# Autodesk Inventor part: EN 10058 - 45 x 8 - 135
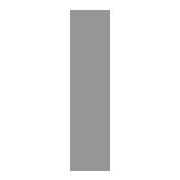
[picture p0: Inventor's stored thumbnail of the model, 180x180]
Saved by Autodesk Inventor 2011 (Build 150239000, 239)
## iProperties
IsCustomPart: 1
Created: 2010-02
Part Number: EN 10058 - 45 x 8 - 135
Material: Steel, A36
Description: flat steel bar 45*8
Document SubType Name: Modeling
Standard: DIN
Designer: PC
Standard Revision: 2004
Standards Organization: DIN
Language: en-US
Size Designation: 45 x 8
Categories: <MemberInstance><Categories><Category DisplayName="Structural Shapes" InternalName="089c4875-fa83-4c05-b084-43b9cc11f5ed" Mnemonic="GRDR"><CategoryParameter Dis
Stock Number: 45 x 8
Density: 7.85 g/cm^3
_CCFamilyMember: 49
_CCFamilyDisplayName: DIN EN 10058 - Hot rolled flat steel bars for general purposes
_FrameMemberDoc: Frame Member File
_Version: 15.0.0
_GetPNFromCC: 1
G_L: 135.000 mm
G_W: 8.000 mm
G_H: 45.000 mm
+D97D2EF8-D0FF-48A2-B9F6-9415A04A1504+CUTDETAIL1: Cut
Author: PC
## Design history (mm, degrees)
node "Start plane"
node "End plane"
sketch "Sketch"
  geometry: L1 (4, -22.5)-(-4, -22.5); L2 (-4, -22.5)-(-4, 22.5); L3 (-4, 22.5)-(4, 22.5); L4 (4, 22.5)-(4, -22.5); L5 (-6, 0)-(8, 0); L6 (0, -30)-(0, 40); L7 (0, 54)-(0, -44) reference; L8 (-9.2, 0)-(13.2, 0) reference
  constraints: 12 end point, 2 collinear, 2 parallel, 1 horizontal, 1 perpendicular
  dimensions: "d0" = 45 distance between parallel lines of L3 L1 (= G_W); "d1" = 8 distance between parallel lines of L4 L2 (= G_H); "d4" = 4 distance between parallel lines of L6 L4 (= 0.5 x d1); "d5" = 22.5 distance between parallel lines of L5 L3 (= 0.5 x d0)
extrude "Body" new body sketch "Sketch" stored distance "d2" = 135 (= G_L); taper "d3" = 0 deg
node "Driven Length"
  sketch "Sketch3"
    geometry: L1 (0, 0)-(10, 0) reference
    constraints: 2 end point, 1 horizontal
  workplane "Work Plane3"
  sketch "Sketch4"
    geometry: L1 (-2, -45)-(12, -45) reference; L2 (-2, 90)-(12, 90) reference
    dimensions: "d9" = 135 distance between parallel lines of L1 L2 (derived)
workplane "Work Plane4"
split "Split1"
body "Solid1"
other parameters: "G_W" = 45 [user parameter; used in 1 equation term], "G_H" = 8 [user parameter; used in 1 equation term], "G_L" = 135 (= d9) [user parameter; used in 1 equation term], "G_OFFSET_START" = 45 [user parameter; used in 1 equation term], "G_OFFSET_END" = 0 [user parameter; used in 1 equation term], "d6" = -45 (= -G_OFFSET_START), "d8" = 90 deg, "MAS" = 0.283 [user parameter]
